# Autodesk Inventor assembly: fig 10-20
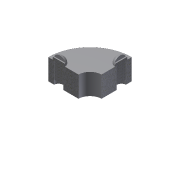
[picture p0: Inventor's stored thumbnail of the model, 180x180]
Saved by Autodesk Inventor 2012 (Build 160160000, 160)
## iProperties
Shininess: 64.0
Angle Display Precision: 2
Document Length Units: 11269
Document Angle Units: 11279
Document Time Units: 11290
Document Mass Units: 11283
Document Length Units Precision: 3
Document Angle Units Precision: 2
Created: 2002-02
Part Number: fig 10-20
Document SubType Name: Assembly
Designer: ***
Density: 0.0
Volumn: 0.0
Area: 0.0
PropertySet Name: Model Information
Control State: 0
Master: False
Checked Out: False
Author: ***
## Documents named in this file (3)
- C:\Users\CadCim\Documents\SAILESH\inventor-2011-fact-prt\c10-inv-2011-prt\c10_inv_2012_prt\fig 10-20.iam
- C:\Users\CadCim\Documents\SAILESH\inventor-2011-fact-prt\c10-inv-2011-prt\c10_inv_2012_prt\Screw.ipt
- C:\Users\CadCim\Documents\SAILESH\inventor-2011-fact-prt\c10-inv-2011-prt\c10_inv_2012_prt\test.ipt
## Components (6 placed, 2 different names)
1. test:1 — Insert:1, Insert:2
2. test:2 — Insert:1
3. Screw:1 — Angle:1, Insert:2
4. Screw:11
5. Screw:12
6. Screw:13
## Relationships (3: Insert 2, Angle 1)
- Insert:1: test:1 ↔ test:2
- Angle:1: Screw:1
- Insert:2: test:1 ↔ Screw:1
